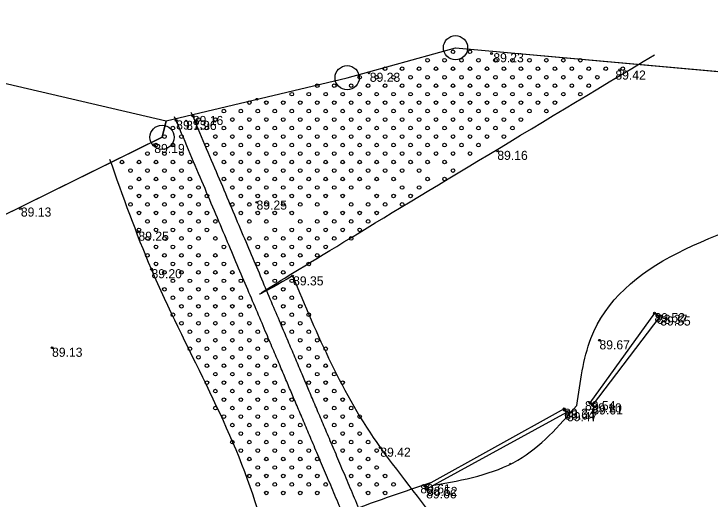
# Model space of a CAD drawing. Extents: x 316000 to 728450, y 314368 to 726000.
# Drawn here: x 726558.9 to 726846, y 316243.5 to 316443.6 of the extents above; entities that cross this region are included whole.
import ezdxf

# ---------------------------------------------------------------- set-up
doc = ezdxf.new("R2010")
doc.units = 0
for name, color, linetype in [('10', 7, 'Continuous'), ('11', 7, 'Continuous'), ('20', 7, 'Continuous'), ('24', 7, 'Continuous'), ('25', 7, 'Continuous'), ('HIDG_ELEM_####_####_#', 7, 'Continuous'), ('HIDG_GRAV_####_####_#', 7, 'Continuous'), ('RAMI_UZMR_####_####_#', 7, 'Continuous'), ('RELJ_AATZ_####_TKST_#', 7, 'Continuous'), ('RELJ_ELEM_####_####_#', 7, 'Continuous'), ('RELJ_HORZ_PAMT_####_#', 7, 'Continuous'), ('TERT_ELEM_####_####_#', 7, 'Continuous'), ('TERT_KONT_####_####_#', 7, 'Continuous')]:
    doc.layers.add(name, color=color, linetype=linetype)

msp = doc.modelspace()

# ---------------------------------------------------------------- linework, layer by layer
at = {"layer": '10'}
msp.add_circle((726620.032, 316392.721), 5, dxfattribs=at)
at = {"layer": '11'}
for centre in [(726741.032, 316429.641), (726696.3359999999, 316417.272)]:
    msp.add_circle(centre, 5, dxfattribs=at)
at = {"layer": '20'}
for p, q in [((726696.336, 316417.272), (726741.032, 316429.641)), ((726741.032, 316429.641), (726920.821, 316413.39300000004)), ((726621.753, 316399.506), (726696.336, 316417.272))]:
    msp.add_line(p, q, dxfattribs=at)
at = {"layer": '24'}
for p, q in [((726621.753, 316399.506), (726620.032, 316392.721)), ((726620.032, 316392.721), (726468.3840000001, 316318.085))]:
    msp.add_line(p, q, dxfattribs=at)
at = {"layer": '25'}
msp.add_line((726476.6112622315, 316433.3648063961), (726621.753, 316399.506), dxfattribs=at)
at = {"layer": 'HIDG_ELEM_####_####_#'}
for centre in [(726629.9608942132, 316399.4937253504), (726824.125, 316319.11100000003), (726797.051, 316282.984), (726785.929, 316280.032), (726729.278, 316248.501)]:
    msp.add_circle(centre, 0.225, dxfattribs=at)
at = {"layer": 'HIDG_GRAV_####_####_#'}
for points in [[(726796.363, 316283.222), (726797.473, 316282.134), (726825.473, 316318.815), (726823.096, 316320.188), (726796.363, 316283.222)], [(726728.314, 316248.84400000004), (726728.9330000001, 316247.504), (726786.98, 316279.34600000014), (726785.855, 316280.73000000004), (726728.314, 316248.84400000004)]]:
    msp.add_lwpolyline(points, dxfattribs=at)
for points in [[(726722.8425711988, 316188.5856627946), (726693.6525711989, 316257.4656627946), (726664.4625711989, 316326.3456627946), (726632.0701371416, 316402.96570215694)], [(726716.3974288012, 316185.85433720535), (726687.2074288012, 316254.73433720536), (726658.0174288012, 316323.61433720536), (726625.1603317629, 316401.20427541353)]]:
    msp.add_open_spline(points, degree=2, dxfattribs=at)
at = {"layer": 'RAMI_UZMR_####_####_#'}
msp.add_lwpolyline([(725661.9970000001, 315676.73000000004), (726089.6880000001, 315915.19), (726207.1789999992, 316075.1470000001), (726354.6642535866, 316148.5881395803), (726468.3839999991, 316318.08500000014), (726620.0319999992, 316392.72100000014), (726621.7529999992, 316399.5060000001), (726696.3359999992, 316417.2720000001), (726741.0319999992, 316429.6410000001), (726920.8209999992, 316413.3930000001), (727228.7119999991, 316639.1820000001)], dxfattribs=at)
at = {"layer": 'RELJ_ELEM_####_####_#'}
for centre in [(726755.9044461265, 316427.2529588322), (726705.3622249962, 316419.27529204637), (726808.8132631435, 316420.5278348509), (726659.0444999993, 316408.389), (726625.8431899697, 316399.66861928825), (726632.7077455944, 316401.5206336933), (726616.6906532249, 316389.5689809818), (726758.27, 316387.12700000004), (726659.0444999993, 316365.8862025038), (726561.4855391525, 316363.3642810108), (726610.1952437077, 316353.6969152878), (726615.6560000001, 316338.30700000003), (726673.856, 316335.498), (726823.096, 316320.188), (726825.473, 316318.815), (726800.3940000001, 316308.976), (726574.652, 316305.913), (726796.363, 316283.222), (726797.473, 316282.134), (726785.855, 316280.73000000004), (726786.98, 316279.346), (726710.0090000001, 316264.689), (726728.314, 316248.84400000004), (726728.9330000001, 316247.504)]:
    msp.add_circle(centre, 0.375, dxfattribs=at)
at = {"layer": 'RELJ_HORZ_PAMT_####_#'}
msp.add_line((726763.3376369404, 316258.352864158), (726763.546366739, 316257.8985164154), dxfattribs=at)
for points in [[(726791.1295800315, 316282.134), (726796.8823604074, 316309.70884742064), (726889.1055072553, 316365.46327240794)], [(726732.0846649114, 316249.21528393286), (726766.7586510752, 316259.54349088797), (726791.1295800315, 316282.134)], [(726669.8574071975, 316227.392357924), (726704.2821152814, 316241.12213399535), (726730.9048203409, 316250.2889154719)]]:
    msp.add_spline(points, degree=3, dxfattribs=at)
at = {"layer": 'TERT_ELEM_####_####_#'}
for centre in [(726740, 316428), (726747, 316428), (726729.5, 316424.5), (726736.5, 316424.5), (726743.5, 316424.5), (726750.5, 316424.5), (726757.5, 316424.5), (726764.5, 316424.5), (726771.5, 316424.5), (726778.5, 316424.5), (726785.5, 316424.5), (726792.5, 316424.5), (726712, 316421), (726719, 316421), (726726, 316421), (726733, 316421), (726740, 316421), (726747, 316421), (726754, 316421), (726761, 316421), (726768, 316421), (726775, 316421), (726782, 316421), (726789, 316421), (726796, 316421), (726803, 316421), (726810, 316421), (726701.5, 316417.5), (726708.5, 316417.5), (726715.5, 316417.5), (726722.5, 316417.5), (726729.5, 316417.5), (726736.5, 316417.5), (726743.5, 316417.5), (726750.5, 316417.5), (726757.5, 316417.5), (726764.5, 316417.5), (726771.5, 316417.5), (726778.5, 316417.5), (726785.5, 316417.5), (726792.5, 316417.5), (726799.5, 316417.5), (726684, 316414), (726691, 316414), (726698, 316414), (726705, 316414), (726712, 316414), (726719, 316414), (726726, 316414), (726733, 316414), (726740, 316414), (726747, 316414), (726754, 316414), (726761, 316414), (726768, 316414), (726775, 316414), (726782, 316414), (726789, 316414), (726796, 316414), (726673.5, 316410.5), (726680.5, 316410.5), (726687.5, 316410.5), (726694.5, 316410.5), (726701.5, 316410.5), (726708.5, 316410.5), (726715.5, 316410.5), (726722.5, 316410.5), (726729.5, 316410.5), (726736.5, 316410.5), (726743.5, 316410.5), (726750.5, 316410.5), (726757.5, 316410.5), (726764.5, 316410.5), (726771.5, 316410.5), (726778.5, 316410.5), (726785.5, 316410.5), (726792.5, 316410.5), (726656, 316407), (726663, 316407), (726670, 316407), (726677, 316407), (726684, 316407), (726691, 316407), (726698, 316407), (726705, 316407), (726712, 316407), (726719, 316407), (726726, 316407), (726733, 316407), (726740, 316407), (726747, 316407), (726754, 316407), (726761, 316407), (726768, 316407), (726775, 316407), (726782, 316407), (726645.5, 316403.5), (726652.5, 316403.5), (726659.5, 316403.5), (726666.5, 316403.5), (726673.5, 316403.5), (726680.5, 316403.5), (726687.5, 316403.5), (726694.5, 316403.5), (726701.5, 316403.5), (726708.5, 316403.5), (726715.5, 316403.5), (726722.5, 316403.5), (726729.5, 316403.5), (726736.5, 316403.5), (726743.5, 316403.5), (726750.5, 316403.5), (726757.5, 316403.5), (726764.5, 316403.5), (726771.5, 316403.5), (726778.5, 316403.5), (726635, 316400), (726642, 316400), (726649, 316400), (726656, 316400), (726663, 316400), (726670, 316400), (726677, 316400), (726684, 316400), (726691, 316400), (726698, 316400), (726705, 316400), (726712, 316400), (726719, 316400), (726726, 316400), (726733, 316400), (726740, 316400), (726747, 316400), (726754, 316400), (726761, 316400), (726768, 316400), (726624.5, 316396.5), (726638.5, 316396.5), (726645.5, 316396.5), (726652.5, 316396.5), (726659.5, 316396.5), (726666.5, 316396.5), (726673.5, 316396.5), (726680.5, 316396.5), (726687.5, 316396.5), (726694.5, 316396.5), (726701.5, 316396.5), (726708.5, 316396.5), (726715.5, 316396.5), (726722.5, 316396.5), (726729.5, 316396.5), (726736.5, 316396.5), (726743.5, 316396.5), (726750.5, 316396.5), (726757.5, 316396.5), (726764.5, 316396.5), (726621, 316393), (726628, 316393), (726642, 316393), (726649, 316393), (726656, 316393), (726663, 316393), (726670, 316393), (726677, 316393), (726684, 316393), (726691, 316393), (726698, 316393), (726705, 316393), (726712, 316393), (726719, 316393), (726726, 316393), (726733, 316393), (726740, 316393), (726747, 316393), (726754, 316393), (726761, 316393), (726617.5, 316389.5), (726624.5, 316389.5), (726638.5, 316389.5), (726645.5, 316389.5), (726652.5, 316389.5), (726659.5, 316389.5), (726666.5, 316389.5), (726673.5, 316389.5), (726680.5, 316389.5), (726687.5, 316389.5), (726694.5, 316389.5), (726701.5, 316389.5), (726708.5, 316389.5), (726715.5, 316389.5), (726722.5, 316389.5), (726729.5, 316389.5), (726736.5, 316389.5), (726743.5, 316389.5), (726750.5, 316389.5), (726614, 316386), (726621, 316386), (726628, 316386), (726642, 316386), (726649, 316386), (726656, 316386), (726663, 316386), (726670, 316386), (726677, 316386), (726684, 316386), (726691, 316386), (726698, 316386), (726705, 316386), (726712, 316386), (726719, 316386), (726726, 316386), (726733, 316386), (726740, 316386), (726747, 316386), (726603.5, 316382.5), (726610.5, 316382.5), (726617.5, 316382.5), (726624.5, 316382.5), (726631.5, 316382.5), (726645.5, 316382.5), (726652.5, 316382.5), (726659.5, 316382.5), (726666.5, 316382.5), (726673.5, 316382.5), (726680.5, 316382.5), (726687.5, 316382.5), (726694.5, 316382.5), (726701.5, 316382.5), (726708.5, 316382.5), (726715.5, 316382.5), (726722.5, 316382.5), (726729.5, 316382.5), (726736.5, 316382.5), (726607, 316379), (726614, 316379), (726621, 316379), (726628, 316379), (726649, 316379), (726656, 316379), (726663, 316379), (726670, 316379), (726677, 316379), (726684, 316379), (726691, 316379), (726698, 316379), (726705, 316379), (726712, 316379), (726719, 316379), (726726, 316379), (726740, 316379), (726610.5, 316375.5), (726617.5, 316375.5), (726624.5, 316375.5), (726631.5, 316375.5), (726645.5, 316375.5), (726652.5, 316375.5), (726659.5, 316375.5), (726666.5, 316375.5), (726673.5, 316375.5), (726680.5, 316375.5), (726687.5, 316375.5), (726694.5, 316375.5), (726701.5, 316375.5), (726708.5, 316375.5), (726715.5, 316375.5), (726729.5, 316375.5), (726736.5, 316375.5), (726607, 316372), (726614, 316372), (726621, 316372), (726628, 316372), (726635, 316372), (726649, 316372), (726656, 316372), (726663, 316372), (726670, 316372), (726677, 316372), (726684, 316372), (726691, 316372), (726698, 316372), (726705, 316372), (726719, 316372), (726726, 316372), (726610.5, 316368.5), (726617.5, 316368.5), (726624.5, 316368.5), (726631.5, 316368.5), (726638.5, 316368.5), (726652.5, 316368.5), (726659.5, 316368.5), (726666.5, 316368.5), (726673.5, 316368.5), (726680.5, 316368.5), (726687.5, 316368.5), (726694.5, 316368.5), (726708.5, 316368.5), (726715.5, 316368.5), (726722.5, 316368.5), (726607, 316365), (726614, 316365), (726621, 316365), (726628, 316365), (726635, 316365), (726649, 316365), (726656, 316365), (726663, 316365), (726670, 316365), (726677, 316365), (726684, 316365), (726698, 316365), (726705, 316365), (726712, 316365), (726719, 316365), (726610.5, 316361.5), (726617.5, 316361.5), (726624.5, 316361.5), (726631.5, 316361.5), (726638.5, 316361.5), (726652.5, 316361.5), (726659.5, 316361.5), (726666.5, 316361.5), (726673.5, 316361.5), (726687.5, 316361.5), (726694.5, 316361.5), (726701.5, 316361.5), (726708.5, 316361.5), (726614, 316358), (726621, 316358), (726628, 316358), (726635, 316358), (726642, 316358), (726656, 316358), (726663, 316358), (726677, 316358), (726684, 316358), (726691, 316358), (726698, 316358), (726705, 316358), (726610.5, 316354.5), (726617.5, 316354.5), (726624.5, 316354.5), (726631.5, 316354.5), (726638.5, 316354.5), (726666.5, 316354.5), (726673.5, 316354.5), (726680.5, 316354.5), (726687.5, 316354.5), (726694.5, 316354.5), (726701.5, 316354.5), (726614, 316351), (726621, 316351), (726628, 316351), (726635, 316351), (726642, 316351), (726656, 316351), (726663, 316351), (726670, 316351), (726677, 316351), (726684, 316351), (726691, 316351), (726698, 316351), (726617.5, 316347.5), (726624.5, 316347.5), (726631.5, 316347.5), (726645.5, 316347.5), (726659.5, 316347.5), (726666.5, 316347.5), (726673.5, 316347.5), (726680.5, 316347.5), (726687.5, 316347.5), (726614, 316344), (726621, 316344), (726628, 316344), (726635, 316344), (726642, 316344), (726663, 316344), (726670, 316344), (726677, 316344), (726684, 316344), (726617.5, 316340.5), (726624.5, 316340.5), (726631.5, 316340.5), (726638.5, 316340.5), (726645.5, 316340.5), (726659.5, 316340.5), (726666.5, 316340.5), (726673.5, 316340.5), (726680.5, 316340.5), (726621, 316337), (726628, 316337), (726635, 316337), (726642, 316337), (726649, 316337), (726663, 316337), (726670, 316337), (726624.5, 316333.5), (726631.5, 316333.5), (726638.5, 316333.5), (726645.5, 316333.5), (726652.5, 316333.5), (726666.5, 316333.5), (726673.5, 316333.5), (726621, 316330), (726628, 316330), (726635, 316330), (726642, 316330), (726649, 316330), (726670, 316330), (726624.5, 316326.5), (726631.5, 316326.5), (726638.5, 316326.5), (726645.5, 316326.5), (726652.5, 316326.5), (726666.5, 316326.5), (726673.5, 316326.5), (726628, 316323), (726635, 316323), (726642, 316323), (726649, 316323), (726656, 316323), (726670, 316323), (726677, 316323), (726624.5, 316319.5), (726631.5, 316319.5), (726638.5, 316319.5), (726645.5, 316319.5), (726652.5, 316319.5), (726673.5, 316319.5), (726680.5, 316319.5), (726628, 316316), (726635, 316316), (726642, 316316), (726649, 316316), (726656, 316316), (726670, 316316), (726677, 316316), (726631.5, 316312.5), (726638.5, 316312.5), (726645.5, 316312.5), (726652.5, 316312.5), (726659.5, 316312.5), (726673.5, 316312.5), (726680.5, 316312.5), (726635, 316309), (726642, 316309), (726649, 316309), (726656, 316309), (726663, 316309), (726677, 316309), (726684, 316309), (726631.5, 316305.5), (726638.5, 316305.5), (726645.5, 316305.5), (726652.5, 316305.5), (726659.5, 316305.5), (726680.5, 316305.5), (726687.5, 316305.5), (726635, 316302), (726642, 316302), (726649, 316302), (726656, 316302), (726663, 316302), (726677, 316302), (726684, 316302), (726638.5, 316298.5), (726645.5, 316298.5), (726652.5, 316298.5), (726659.5, 316298.5), (726666.5, 316298.5), (726680.5, 316298.5), (726687.5, 316298.5), (726642, 316295), (726649, 316295), (726656, 316295), (726663, 316295), (726684, 316295), (726691, 316295), (726638.5, 316291.5), (726645.5, 316291.5), (726652.5, 316291.5), (726659.5, 316291.5), (726666.5, 316291.5), (726680.5, 316291.5), (726687.5, 316291.5), (726694.5, 316291.5), (726642, 316288), (726649, 316288), (726656, 316288), (726663, 316288), (726670, 316288), (726684, 316288), (726691, 316288), (726645.5, 316284.5), (726652.5, 316284.5), (726659.5, 316284.5), (726666.5, 316284.5), (726673.5, 316284.5), (726687.5, 316284.5), (726694.5, 316284.5), (726642, 316281), (726649, 316281), (726656, 316281), (726663, 316281), (726670, 316281), (726691, 316281), (726698, 316281), (726645.5, 316277.5), (726652.5, 316277.5), (726659.5, 316277.5), (726666.5, 316277.5), (726673.5, 316277.5), (726687.5, 316277.5), (726694.5, 316277.5), (726701.5, 316277.5), (726649, 316274), (726656, 316274), (726663, 316274), (726670, 316274), (726677, 316274), (726691, 316274), (726698, 316274), (726652.5, 316270.5), (726659.5, 316270.5), (726666.5, 316270.5), (726673.5, 316270.5), (726694.5, 316270.5), (726701.5, 316270.5), (726649, 316267), (726656, 316267), (726663, 316267), (726670, 316267), (726677, 316267), (726691, 316267), (726698, 316267), (726705, 316267), (726652.5, 316263.5), (726659.5, 316263.5), (726666.5, 316263.5), (726673.5, 316263.5), (726680.5, 316263.5), (726694.5, 316263.5), (726701.5, 316263.5), (726708.5, 316263.5), (726656, 316260), (726663, 316260), (726670, 316260), (726677, 316260), (726684, 316260), (726698, 316260), (726705, 316260), (726659.5, 316256.5), (726666.5, 316256.5), (726673.5, 316256.5), (726680.5, 316256.5), (726701.5, 316256.5), (726708.5, 316256.5), (726656, 316253), (726663, 316253), (726670, 316253), (726677, 316253), (726684, 316253), (726698, 316253), (726705, 316253), (726712, 316253), (726659.5, 316249.5), (726666.5, 316249.5), (726673.5, 316249.5), (726680.5, 316249.5), (726687.5, 316249.5), (726701.5, 316249.5), (726708.5, 316249.5), (726715.5, 316249.5), (726663, 316246), (726670, 316246), (726677, 316246), (726684, 316246), (726705, 316246), (726712, 316246)]:
    msp.add_circle(centre, 0.75, dxfattribs=at)
at = {"layer": 'TERT_KONT_####_####_#'}
for points in [[(726673.8598212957, 316335.5001887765), (726673.856, 316335.498), (726823.1030390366, 316426.77996008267)], [(726673.856, 316335.498), (726710.0090000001, 316264.689), (726746.0872619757, 316187.6062783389), (726717.3320000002, 316148.085), (726690.508, 316164.743), (726658.4350000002, 316242.392), (726615.6560000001, 316338.307), (726598.5356309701, 316383.58358696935)]]:
    msp.add_spline(points, degree=3, dxfattribs=at)

# ---------------------------------------------------------------- texts
at = {"layer": 'RELJ_AATZ_####_TKST_#'}
for s, p in [('89.23', (726756.638, 316423.64400000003)), ('89.42', (726806.953, 316416.498)), ('89.23', (726705.687, 316415.59400000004)), ('89.13', (726625.843, 316395.919)), ('87.96', (726629.961, 316395.744)), ('89.16', (726632.708, 316397.771)), ('89.19', (726616.81, 316386.216)), ('89.16', (726758.27, 316383.37700000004)), ('89.25', (726658.9770000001, 316362.873)), ('89.13', (726561.7960000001, 316359.994)), ('89.25', (726610.27, 316350.038)), ('89.20', (726615.6560000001, 316334.55700000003)), ('89.35', (726674.044, 316331.615)), ('89.52', (726823.096, 316316.438)), ('88.37', (726824.125, 316315.756)), ('89.55', (726825.473, 316315.065)), ('89.67', (726800.3940000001, 316305.226)), ('89.13', (726574.652, 316302.163)), ('89.54', (726794.419, 316280.12)), ('89.10', (726797.051, 316279.234)), ('89.61', (726797.473, 316278.384)), ('89.33', (726785.855, 316276.98000000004)), ('88.64', (726785.929, 316276.282)), ('89.47', (726786.98, 316275.596)), ('89.42', (726710.0090000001, 316260.939)), ('89.61', (726726.5160000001, 316245.835)), ('89.66', (726728.9330000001, 316243.754)), ('88.52', (726729.278, 316244.751))]:
    msp.add_text(s, height=3.75, dxfattribs=at).set_placement(p)

doc.saveas('drawing.dxf')
